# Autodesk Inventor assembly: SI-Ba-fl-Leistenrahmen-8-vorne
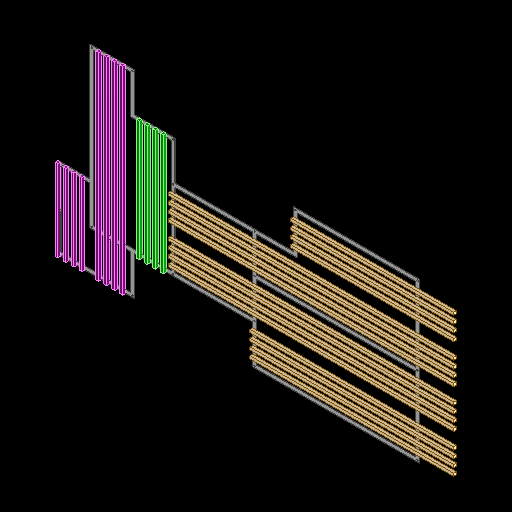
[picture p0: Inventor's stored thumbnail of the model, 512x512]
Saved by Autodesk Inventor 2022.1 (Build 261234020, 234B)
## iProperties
Created: 2021-12
Part Number: SI-Ba-fl-Leistenrahmen-8-vorne
Document SubType Name: Assembly
Designer: Ruhl
Author: Ruhl
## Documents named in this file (8)
- N:\INVENTOR\Schlegel\2022\P22-0037\Module\SI\Si-Ba-fl_Sitzbank-flach\Si-Ba-fl_2\SI-Ba-fl-Leistenrahmen-8-vorne.iam
- N:\INVENTOR\Schlegel\2022\P22-0037\Module\SI\Si-Ba-fl_Sitzbank-flach\Si-Ba-fl_2\Gitter\SI-Ba-fl-Metallrahmen-8-vorne.ipt
- N:\INVENTOR\Schlegel\2022\P22-0037\Module\SI\Si-Ba-fl_Sitzbank-flach\Si-Ba-fl_2\Gitter\SI-Ba-fl-Stab-440-H2.ipt
- N:\INVENTOR\Schlegel\2022\P22-0037\Module\SI\Si-Ba-fl_Sitzbank-flach\Si-Ba-fl_2\Gitter\SI-Ba-fl-Stab-1070-H2.ipt
- N:\INVENTOR\Schlegel\2022\P22-0037\Module\SI\Si-Ba-fl_Sitzbank-flach\Si-Ba-fl_2\Gitter\SI-Ba-fl-Stab-650-H4.ipt
- N:\INVENTOR\Schlegel\2022\P22-0037\Module\SI\Si-Ba-fl_Sitzbank-flach\Si-Ba-fl_2\Gitter\SI-Ba-fl-Stab-880-H3.ipt
- N:\INVENTOR\Schlegel\2022\P22-0037\Module\SI\Si-Ba-fl_Sitzbank-flach\Si-Ba-fl_2\Gitter\SI-Ba-fl-Stab-1540-H3.ipt
- N:\INVENTOR\Schlegel\2022\P22-0037\Module\SI\Si-Ba-fl_Sitzbank-flach\Si-Ba-fl_2\Gitter\SI-Ba-fl-Stab-1100-H3.ipt
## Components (29 placed, 7 different names)
1. SI-Ba-fl-Metallrahmen-8-vorne:1 — Fluchtend:1, Passend:1, Passend:2, Passend:3, Fluchtend:2, Passend:4, Passend:5, Fluchtend:3, Passend:6, Passend:7, Passend:8, Fluchtend:4, Passend:9, Fluchtend:5, Passend:10, Passend:11, Fluchtend:6, Passend:12
2. SI-Ba-fl-Stab-440-H2:1 — Fluchtend:1, Passend:1, Passend:2
3. SI-Ba-fl-Stab-440-H2:2
4. SI-Ba-fl-Stab-440-H2:3
5. SI-Ba-fl-Stab-440-H2:4
6. SI-Ba-fl-Stab-1070-H2:1 — Passend:3, Fluchtend:2, Passend:4
7. SI-Ba-fl-Stab-1070-H2:2
8. SI-Ba-fl-Stab-1070-H2:3
9. SI-Ba-fl-Stab-1070-H2:4
10. SI-Ba-fl-Stab-650-H4:1 — Passend:5, Fluchtend:3, Passend:6
11. SI-Ba-fl-Stab-650-H4:2
12. SI-Ba-fl-Stab-650-H4:3
13. SI-Ba-fl-Stab-650-H4:4
14. SI-Ba-fl-Stab-880-H3:1 — Passend:7, Passend:8, Fluchtend:4
15. SI-Ba-fl-Stab-880-H3:2
16. SI-Ba-fl-Stab-880-H3:3
17. SI-Ba-fl-Stab-880-H3:4
18. SI-Ba-fl-Stab-1100-H3:1 — Passend:11, Fluchtend:6, Passend:12
19. SI-Ba-fl-Stab-1100-H3:2
20. SI-Ba-fl-Stab-1100-H3:3
21. SI-Ba-fl-Stab-1100-H3:4
22. SI-Ba-fl-Stab-1540-H3:1 — Passend:9, Fluchtend:5, Passend:10
23. SI-Ba-fl-Stab-1540-H3:2
24. SI-Ba-fl-Stab-1540-H3:3
25. SI-Ba-fl-Stab-1540-H3:4
26. SI-Ba-fl-Stab-1540-H3:5
27. SI-Ba-fl-Stab-1540-H3:6
28. SI-Ba-fl-Stab-1540-H3:7
29. SI-Ba-fl-Stab-1540-H3:8
## Component patterns: Komponentenanordnung 5:2 (4 elements)
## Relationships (18: Mate 12, Flush 6)
- Fluchtend:1 [Flush]: SI-Ba-fl-Metallrahmen-8-vorne:1 ↔ SI-Ba-fl-Stab-440-H2:1
- Passend:1 [Mate]: SI-Ba-fl-Metallrahmen-8-vorne:1 ↔ SI-Ba-fl-Stab-440-H2:1
- Passend:2 [Mate]: SI-Ba-fl-Metallrahmen-8-vorne:1 ↔ SI-Ba-fl-Stab-440-H2:1
- Passend:3 [Mate]: SI-Ba-fl-Metallrahmen-8-vorne:1 ↔ SI-Ba-fl-Stab-1070-H2:1
- Fluchtend:2 [Flush]: SI-Ba-fl-Metallrahmen-8-vorne:1 ↔ SI-Ba-fl-Stab-1070-H2:1
- Passend:4 [Mate]: SI-Ba-fl-Metallrahmen-8-vorne:1 ↔ SI-Ba-fl-Stab-1070-H2:1
- Passend:5 [Mate]: SI-Ba-fl-Metallrahmen-8-vorne:1 ↔ SI-Ba-fl-Stab-650-H4:1
- Fluchtend:3 [Flush]: SI-Ba-fl-Metallrahmen-8-vorne:1 ↔ SI-Ba-fl-Stab-650-H4:1
- Passend:6 [Mate]: SI-Ba-fl-Metallrahmen-8-vorne:1 ↔ SI-Ba-fl-Stab-650-H4:1
- Passend:7 [Mate]: SI-Ba-fl-Metallrahmen-8-vorne:1 ↔ SI-Ba-fl-Stab-880-H3:1
- Passend:8 [Mate]: SI-Ba-fl-Metallrahmen-8-vorne:1 ↔ SI-Ba-fl-Stab-880-H3:1
- Fluchtend:4 [Flush]: SI-Ba-fl-Metallrahmen-8-vorne:1 ↔ SI-Ba-fl-Stab-880-H3:1
- Passend:9 [Mate]: SI-Ba-fl-Metallrahmen-8-vorne:1 ↔ SI-Ba-fl-Stab-1540-H3:1
- Fluchtend:5 [Flush]: SI-Ba-fl-Metallrahmen-8-vorne:1 ↔ SI-Ba-fl-Stab-1540-H3:1
- Passend:10 [Mate]: SI-Ba-fl-Metallrahmen-8-vorne:1 ↔ SI-Ba-fl-Stab-1540-H3:1
- Passend:11 [Mate]: SI-Ba-fl-Metallrahmen-8-vorne:1 ↔ SI-Ba-fl-Stab-1100-H3:1
- Fluchtend:6 [Flush]: SI-Ba-fl-Metallrahmen-8-vorne:1 ↔ SI-Ba-fl-Stab-1100-H3:1
- Passend:12 [Mate]: SI-Ba-fl-Metallrahmen-8-vorne:1 ↔ SI-Ba-fl-Stab-1100-H3:1
